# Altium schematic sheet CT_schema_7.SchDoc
size 278 x 170 mm
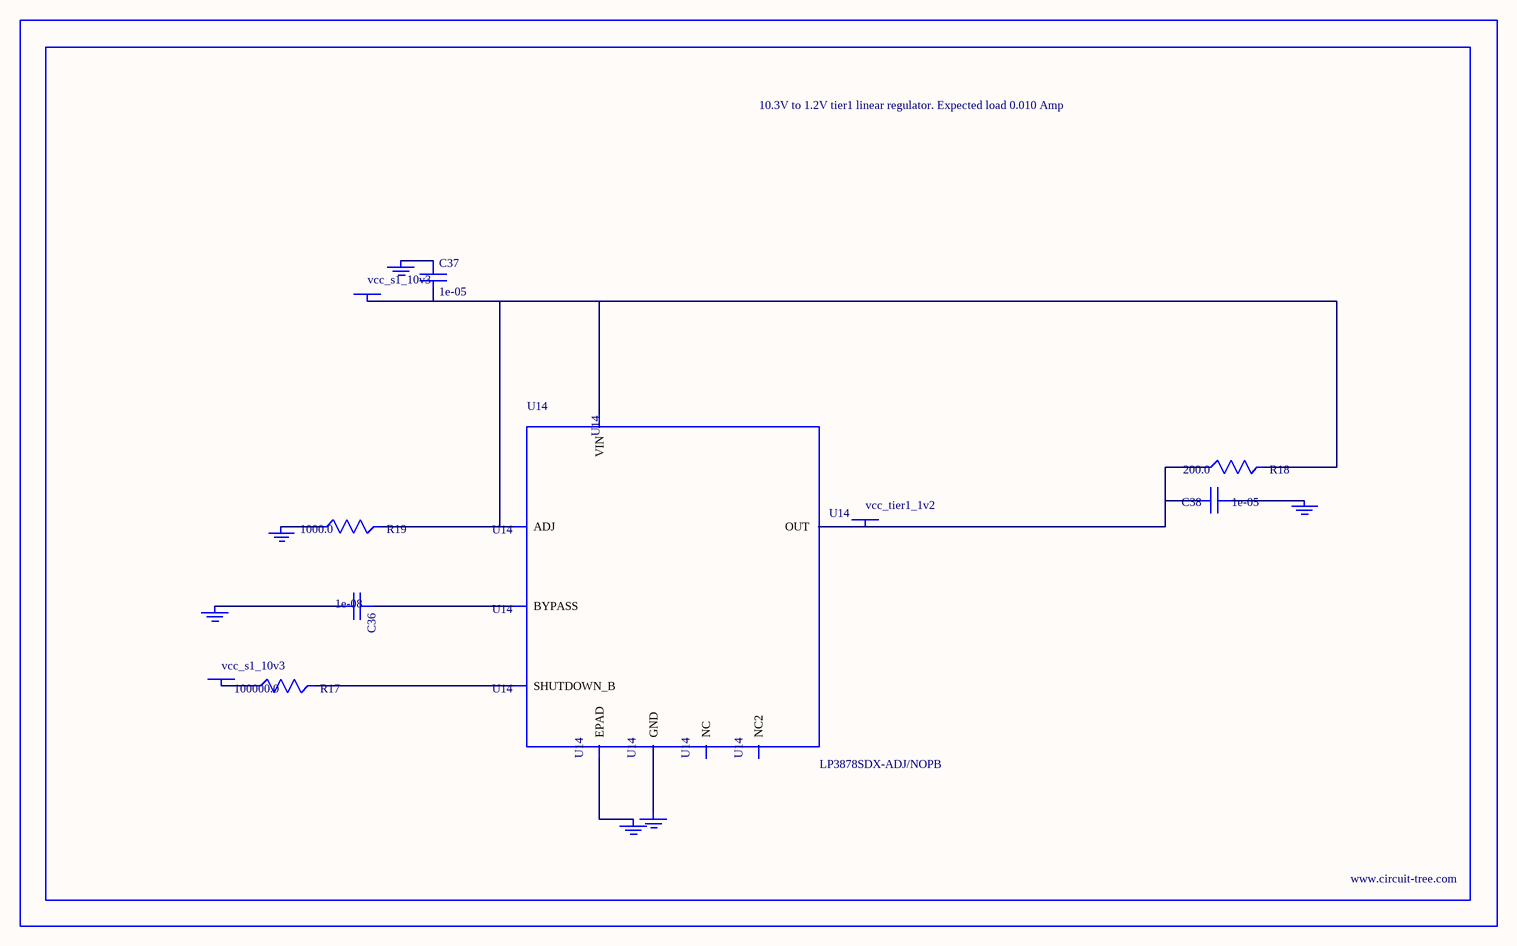
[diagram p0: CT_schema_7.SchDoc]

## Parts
BORDER6  (no value)
C36  1e-08  [C0402]
C37  1e-05  [C1206]
C38  1e-05  [C0805]
GND_INSTANCE_6_0  (no value)
GND_INSTANCE_6_1  (no value)
GND_INSTANCE_6_2  (no value)
GND_INSTANCE_6_3  (no value)
GND_INSTANCE_6_4  (no value)
GND_INSTANCE_6_5  (no value)
POWER_INSTANCE_6_0  vcc_s1_10v3
POWER_INSTANCE_6_1  vcc_s1_10v3
POWER_INSTANCE_6_2  vcc_tier1_1v2
R17  100000.0  [R0603]
R18  200.0  [R0603]
R19  1000.0  [R0603]
U14  LP3878SDX-ADJ/NOPB  [WSON-8]

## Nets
NetC36_1: C36.1 U14.1(BYPASS)
NetC36_2: C36.2 GND_INSTANCE_6_0.0(GND)
NetC37_1: C37.1 GND_INSTANCE_6_1.0(GND)
NetC37_2: C37.2 POWER_INSTANCE_6_0.0(PWR) R18.2 R19.2 U14.4(VIN) U14.6(ADJ)
NetC38_1: C38.1 GND_INSTANCE_6_2.0(GND)
NetC38_2: C38.2 POWER_INSTANCE_6_2.0(PWR) R18.1 U14.5(OUT)
NetGND_INSTANCE_6_3_0: GND_INSTANCE_6_3.0(GND) R19.1
NetGND_INSTANCE_6_4_0: GND_INSTANCE_6_4.0(GND) U14.PAD(EPAD)
NetGND_INSTANCE_6_5_0: GND_INSTANCE_6_5.0(GND) U14.3(GND)
NetPOWER_INSTANCE_6_1_0: POWER_INSTANCE_6_1.0(PWR) R17.1
NetR17_2: R17.2 U14.8(SHUTDOWN_B)

Not connected (* = marked no-connect by the designer): U14 2(NC) 7(NC2)

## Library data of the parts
BORDER6 = BORDER_PAGE6
C36 = C0402C103K3RAC
C37 = C1206C106K3RACTU
C38 = GRM219R60J106ME19D
GND_INSTANCE_6_0-GND_INSTANCE_6_5 = GND
POWER_INSTANCE_6_0-POWER_INSTANCE_6_2 = PWR
R17 = RC0603JR-07100KL
R18 = RC0603JR-07200RL
R19 = RC0603JR-071KL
